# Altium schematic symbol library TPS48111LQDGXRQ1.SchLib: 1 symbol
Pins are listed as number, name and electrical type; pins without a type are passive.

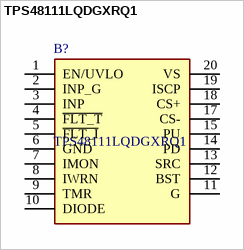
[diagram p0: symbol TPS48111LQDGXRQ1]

## TPS48111LQDGXRQ1
designator B?
TPS4811-Q1 100V Automotive Smart High-Side Driver With Protection and Diagnostics , 3.5V ~ 80V , 4A , 19-VSSOP ,-40C ~ 125C (TA); Manufacturer_Name: Texas Instruments; Geometry.Height: 1.1mm
footprint TPS48111LQDGXRQ1
pins: 1 EN/UVLO, 2 INP_G, 3 INP, 4 ~{FLT_T}, 5 ~{FLT_I}, 6 GND, 7 IMON, 8 IWRN, 9 TMR, 10 DIODE, 11 G, 12 BST, 13 SRC, 14 PD, 15 PU, 17 CS-, 18 CS+, 19 ISCP, 20 VS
